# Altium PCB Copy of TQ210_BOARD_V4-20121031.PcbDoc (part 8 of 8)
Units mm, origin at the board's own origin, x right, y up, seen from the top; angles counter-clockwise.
Board outline 191.2 x 131.27 mm, 2 copper layers (TopLayer, BottomLayer); 362 components, 455 nets, 1594 pads, 630 vias.
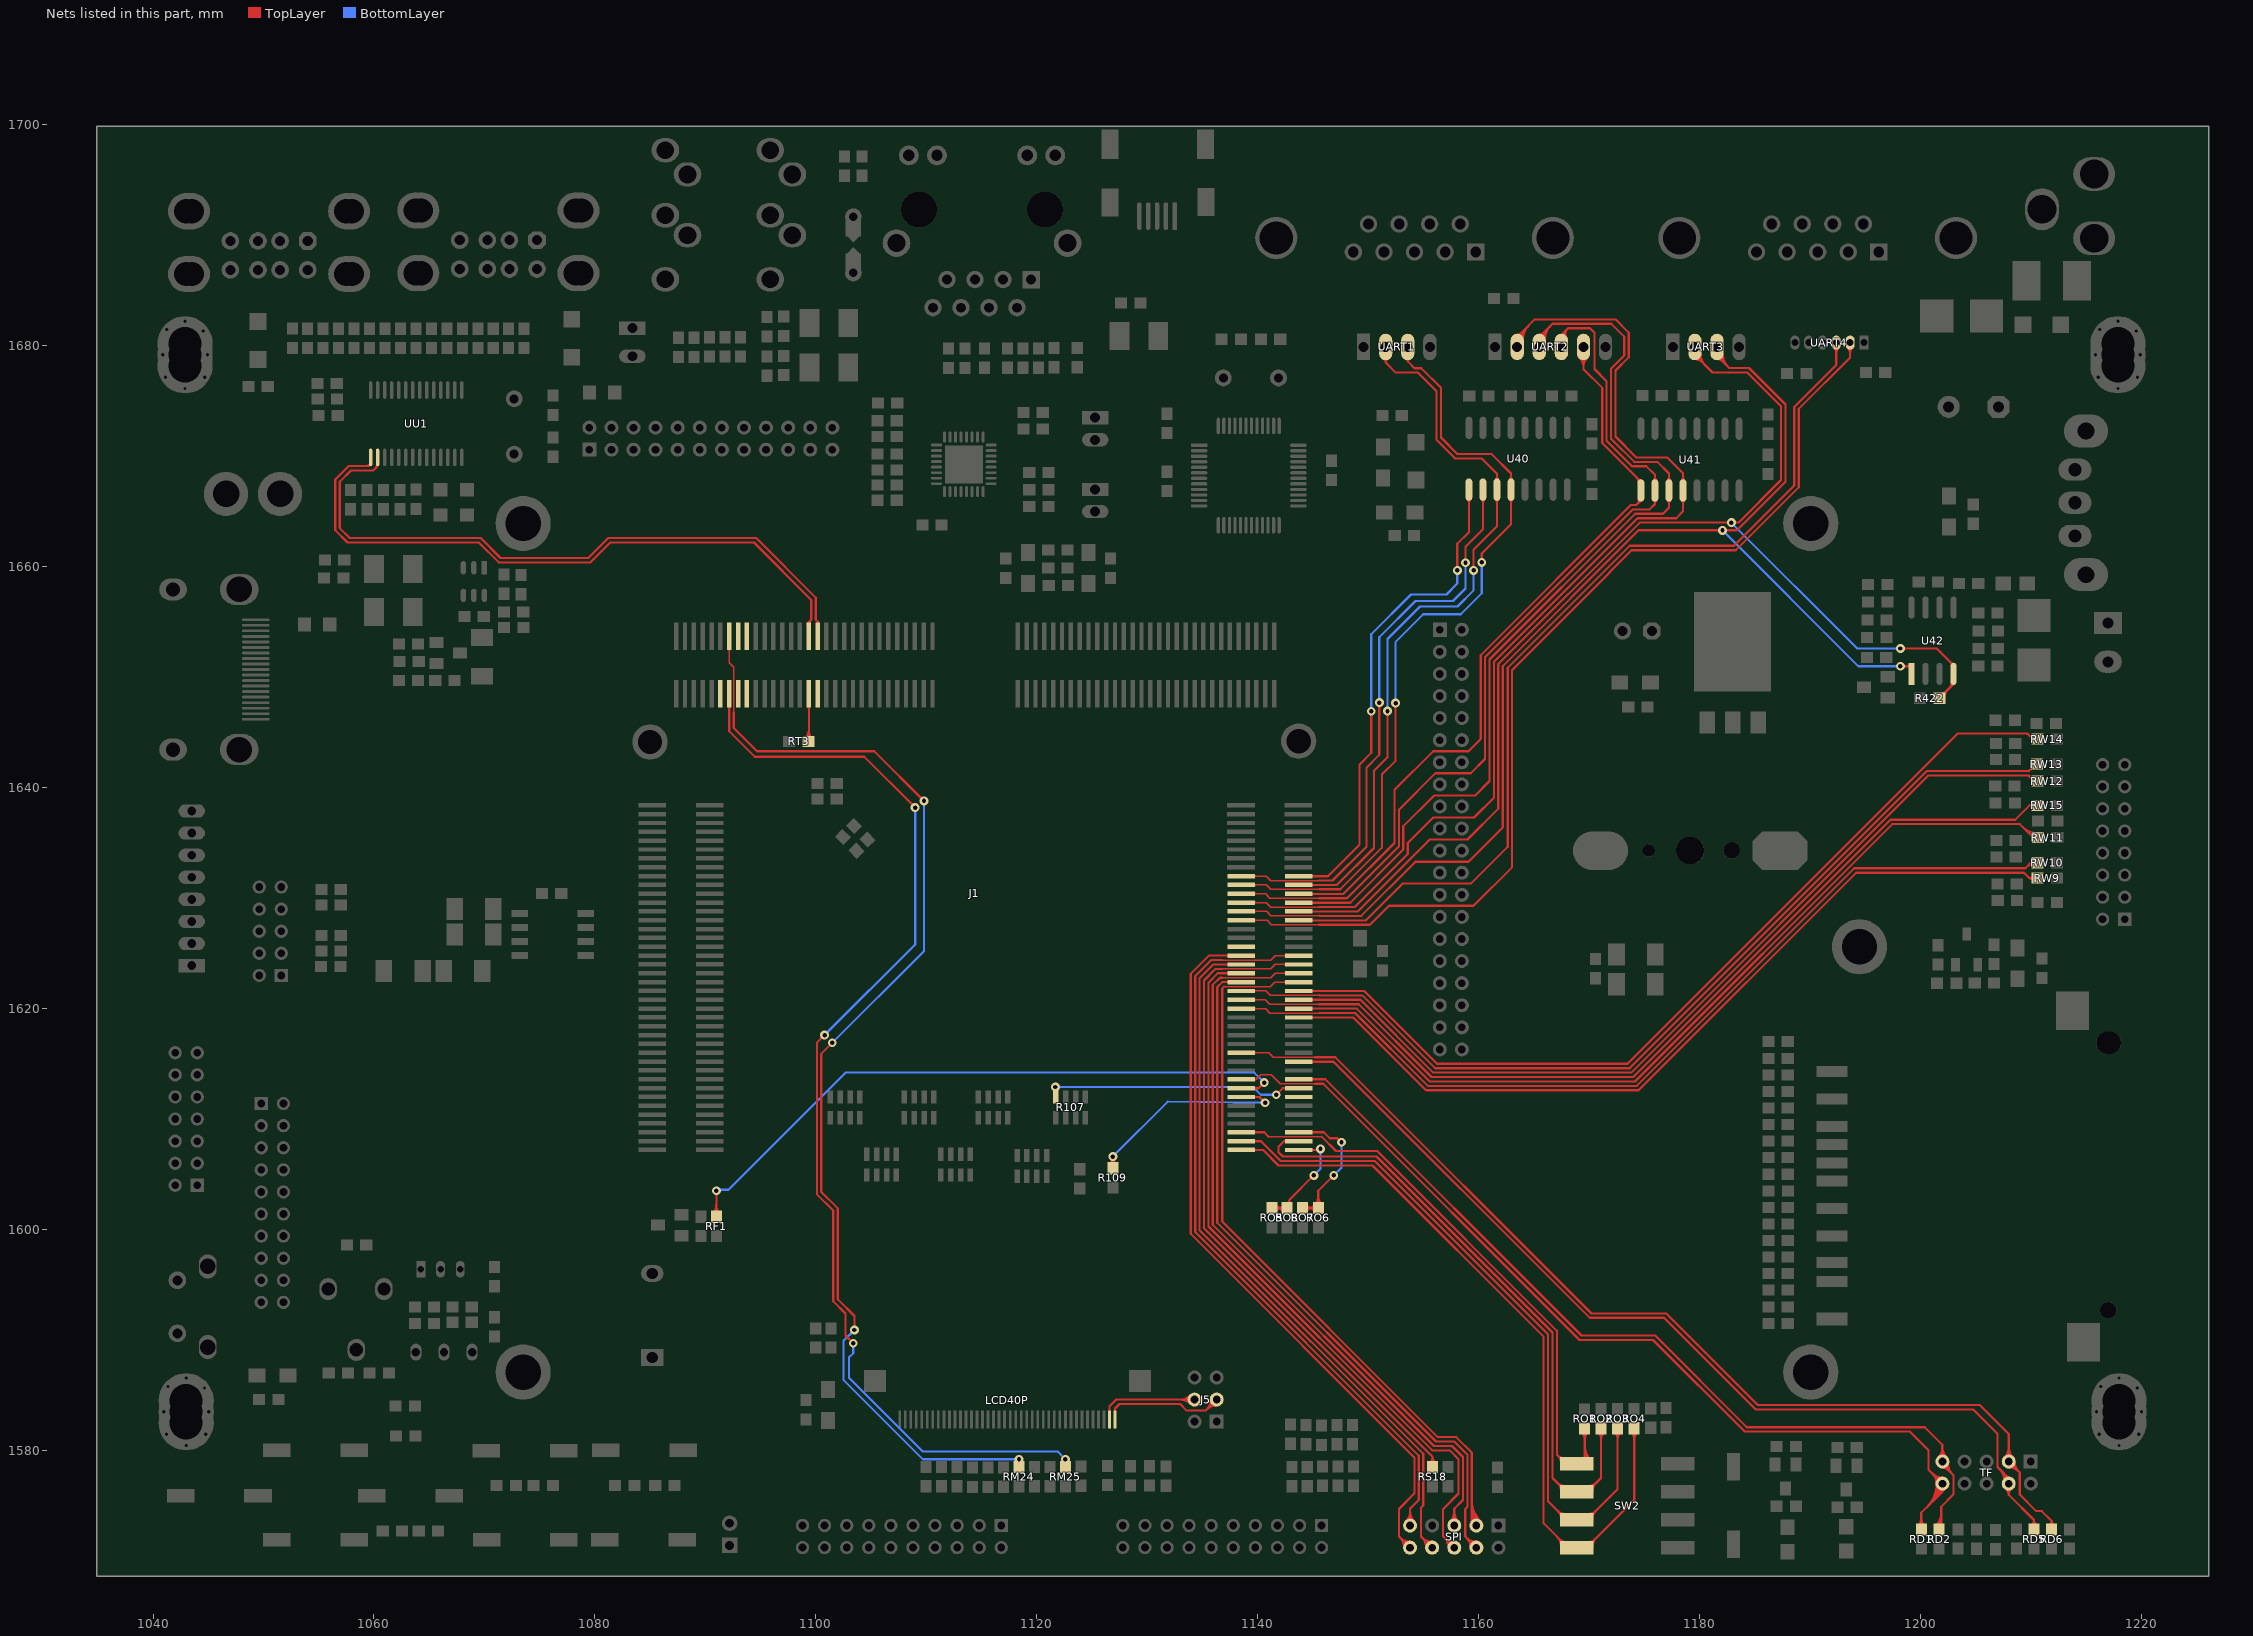
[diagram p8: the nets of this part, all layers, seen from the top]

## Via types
v1: diameter 1, hole 0.5, TopLayer to BottomLayer, 458 vias
v2: diameter 0.8, hole 0.4, TopLayer to BottomLayer, 172 vias

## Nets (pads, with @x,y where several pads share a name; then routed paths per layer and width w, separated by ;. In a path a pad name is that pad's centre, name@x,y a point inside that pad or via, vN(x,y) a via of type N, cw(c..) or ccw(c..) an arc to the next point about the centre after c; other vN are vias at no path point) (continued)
XMMC1DATA0: J1.263 RD2.2 TF.9 | length 89.9
  TopLayer w0.2: J1.263@1143.715,1613.595 1146.129,1613.595 1169.323,1590.4 1176,1590.4 1184.3,1582.1 1200.4,1582.1 1202,1580.5 TF.9@1202,1579 ; RD2.2@1201.417,1573.183 ccw(c1200.251,1574.349) 1201.9,1574.349 ; RD2.2@1201.559,1573.041 ccw(c1200.734,1573.866) 1201.9,1573.866 ; TF.9@1201.633,1579.367 ccw(c1200.746,1580.254) 1202,1580.254 ; RD2.2@1201.7,1572.9 ccw(c1201.217,1573.383) 1201.9,1573.383 ccw(c1202.183,1573.383) RD2.2@1201.983,1573.183 ; TF.9@1201.774,1579.226 ccw(c1201.229,1579.771) 1202,1579.771 ; RD2.2@1201.9,1572.85 1201.9,1574.9 1203,1576 1203,1577.75 1202.011,1578.739 TF.9@1202.011,1578.989 ; 1202,1579.824 ccw(c1202.846,1579.824) TF.9@1202.248,1579.226 ; 1202,1580.307 ccw(c1203.329,1580.307) TF.9@1202.389,1579.367 ; TF.9@1202.011,1578.454 cw(c1202.011,1577.765) 1202.498,1578.252 ; TF.9@1202.144,1578.968 ccw(c1202.759,1578.871) 1202.319,1578.431 ; TF.9@1202.342,1578.937 ccw(c1203.24,1578.796) 1202.597,1578.153 ; TF.9@1202.54,1578.906 ccw(c1203.72,1578.72) 1202.875,1577.875
XMMC1DATA1: J1.264 RD1.2 TF.10 | length 99
  TopLayer w0.135: J1.264@1138.515,1613.595 1139.9,1613.595 1140.305,1614 1141.234,1614 1142.039,1613.194 1145.194,1613.194 1145.2,1613.2 ; J1.264@1139.658,1613.501 cw(c1139.884,1613.275) 1139.884,1613.595 cw(c1139.884,1613.914) J1.264@1139.658,1613.688
  TopLayer w0.2: 1145.2,1613.2 1145.957,1613.2 1145.957,1613.195 1169.152,1590 1175.8,1590 1184.1,1581.7 1199.05,1581.7 1200.75,1580 1200.75,1578.25 TF.10@1202.011,1576.989 1202.011,1576.261 ; RD1.2@1199.817,1573.183 ccw(c1199.134,1573.866) 1200.1,1573.866 ccw(c1201.066,1573.866) RD1.2@1200.383,1573.183 ; RD1.2@1200.1,1572.85 1200.1,1574.35 1202.011,1576.261 ; 1200.583,1574.833 ccw(c1198.427,1576.989) 1201.476,1576.989 ccw(c1200.184,1576.989) 1201.098,1577.902 ccw(c1202.011,1578.815) TF.10@1202.011,1577.524 ; 1200.925,1575.175 ccw(c1199.11,1576.989) 1201.676,1576.989 ccw(c1200.867,1576.989) 1201.439,1577.561 ccw(c1202.011,1578.133) TF.10@1202.011,1577.324 ; 1201.266,1575.516 ccw(c1199.793,1576.989) TF.10@1201.876,1576.989 ; 1201.607,1575.857 ccw(c1200.476,1576.989) TF.10@1202.076,1576.989 ; TF.10@1201.851,1576.478 cw(c1201.784,1576.261) 1202.011,1576.261 ; 1201.949,1576.199 ccw(c1201.159,1576.989) TF.10@1202.276,1576.989 ; TF.10@1202.171,1576.478 ccw(c1202.239,1576.261) 1202.011,1576.261
XMMC1DATA2: J1.258 RD6.2 TF.3 | length 102.3
  TopLayer w0.135: J1.258@1138.515,1615.995 1141,1615.995 1141.401,1615.593 1145.193,1615.593 ; J1.258@1139.658,1615.901 cw(c1139.884,1615.675) 1139.884,1615.995 cw(c1139.884,1616.314) J1.258@1139.658,1616.088
  TopLayer w0.2: 1145.2,1615.6 1145.205,1615.595 1147.036,1615.595 1170.231,1592.4 1177,1592.4 1185.3,1584.1 1205.4,1584.1 1208.011,1581.489 TF.3@1208.011,1578.989 1209,1578 1209,1576 1210.5,1574.5 1211,1574.5 1211.9,1573.6 ; TF.3@1207.633,1579.367 ccw(c1206.719,1580.28) 1208.011,1580.28 ccw(c1209.303,1580.28) TF.3@1208.389,1579.367 ; TF.3@1207.774,1579.226 ccw(c1207.202,1579.798) 1208.011,1579.798 ccw(c1208.82,1579.798) TF.3@1208.248,1579.226 ; TF.3@1208.011,1578.454 cw(c1208.011,1577.162) 1208.924,1578.075 cw(c1209.838,1578.989) TF.3@1208.546,1578.989 ; TF.3@1208.011,1578.654 cw(c1208.011,1577.845) 1208.583,1578.417 cw(c1209.155,1578.989) TF.3@1208.346,1578.989 ; RD6.2@1211.697,1573.245 ccw(c1211.488,1573.6) 1211.9,1573.6 ; RD6.2@1211.9,1572.85 1211.9,1573.6 ; RD6.2@1212.103,1573.245 cw(c1212.312,1573.6) 1211.9,1573.6
XMMC1DATA3: J1.259 RD5.2 TF.4 | length 93.3
  TopLayer w0.2: J1.259@1143.715,1615.195 1146.871,1615.195 1170.065,1592 1176.8,1592 1178.162,1590.638 1185.1,1583.7 1204.8,1583.7 1207,1581.5 1207,1578.5 1208.011,1577.489 1208.011,1575.989 ; 1207.09,1578.41 cw(c1205.675,1576.995) TF.4@1207.676,1576.99 ; 1207.43,1578.07 cw(c1206.354,1576.993) TF.4@1207.876,1576.989 ; TF.4@1207.714,1576.544 cw(c1207.344,1575.989) 1208.011,1575.989 ; 1207.77,1577.73 cw(c1207.032,1576.992) TF.4@1208.076,1576.989 ; TF.4@1208.308,1576.544 ccw(c1208.678,1575.989) 1208.011,1575.989 ; RD5.2@1210.06,1573.22 ccw(c1209.7,1573.7) 1210.3,1573.7 ; RD5.2@1210.3,1572.85 1210.3,1573.7 ; RD5.2@1210.54,1573.22 cw(c1210.9,1573.7) 1210.3,1573.7 ; 1208.011,1575.989 1210.3,1573.7
XMMC2CDN: J1.92
XMMC2CLK: J1.96
XMMC2CMD: J1.95
XMMC2DATA0: J1.97 | length 0
  TopLayer w0.2: J1.97@1093.765,1653.697 J1.97@1093.775,1653.707
XMMC2DATA1: J1.98
XMMC2DATA2: J1.93 RM24.2 | length 105.7
  TopLayer w0.135: J1.93@1092.071,1652.553 cw(c1091.845,1652.327) 1092.165,1652.327 cw(c1092.484,1652.327) J1.93@1092.258,1652.553 ; J1.93@1092.165,1653.697 1092.165,1651.315 1092.564,1650.916 1092.564,1646.826
  TopLayer w0.2: 1092.581,1646.809 1092.581,1645.4 1094.681,1643.3 1105.3,1643.3 v2(1109.8,1638.8) ; v2(1101.5,1616.9) 1100.5,1615.9 1100.5,1603.4 1101.99,1601.91 1101.99,1593.676 1103.5,1592.166 v2(1103.5,1590.9)
  BottomLayer w0.2: v2(1101.5,1616.9) 1109.8,1625.2 v2(1109.8,1638.8) ; v2(1103.5,1590.9) 1102.5,1589.9 1102.5,1586.4 1109.7,1579.2 v2(1118.4,1579.2)
XMMC2DATA3: J1.94 RM25.2 | length 102.6
  TopLayer w0.2: J1.94@1092.175,1648.487 1092.175,1645.1 1094.475,1642.8 1104.4,1642.8 v2(1109,1638.2) ; v2(1100.8,1617.6) 1100.1,1616.9 1100.1,1603.2 1101.59,1601.71 1101.59,1593.51 1102.7,1592.4 1102.7,1590.4 v2(1103.4,1589.7)
  BottomLayer w0.2: v2(1100.8,1617.6) 1109,1625.8 v2(1109,1638.2) ; v2(1103.4,1589.7) 1103.4,1588.8 1103,1588.4 1103,1586.6 1109.7,1579.9 1121.9,1579.9 v2(1122.6,1579.2)
XMMC3CDN: J1.246 RW15.1 | length 86.5
  TopLayer w0.135: J1.246@1138.515,1620.795 1140.716,1620.795 1141.115,1620.395 1145.594,1620.395 ; J1.246@1139.658,1620.701 cw(c1139.884,1620.475) 1139.884,1620.795 cw(c1139.884,1621.114) J1.246@1139.658,1620.888
  TopLayer w0.2: 1145.595,1620.395 1145.6,1620.4 ; 1145.605,1620.395 1149.158,1620.395 1155.753,1613.8 1174.003,1613.8 1197.303,1637.1 1208.6,1637.1 1209.905,1638.405 ; RW15.1@1210.218,1638.217 ccw(c1209.905,1638.05) 1209.905,1638.405 ; RW15.1@1210.218,1638.593 cw(c1209.905,1638.76) 1209.905,1638.405 ; RW15.1@1210.621,1638.405 1209.905,1638.405
XMMC3CLK: J1.247 RW11.1 | length 82.7
  TopLayer w0.2: J1.247@1143.715,1619.995 1148.993,1619.995 1155.587,1613.4 1174.169,1613.4 1197.469,1636.7 1209,1636.7 RW11.1@1210.2,1635.5 ; 1209.268,1636.432 ccw(c1210.615,1637.778) RW11.1@1210.615,1635.874 ; 1209.61,1636.09 ccw(c1210.615,1637.095) RW11.1@1210.615,1635.674 ; 1209.951,1635.749 ccw(c1210.615,1636.412) RW11.1@1210.615,1635.474
XMMC3CMD: J1.245 RW12.1 | length 81.7
  TopLayer w0.2: J1.245@1143.715,1620.795 1149.324,1620.795 1155.919,1614.2 1173.837,1614.2 1200.737,1641.1 1209.8,1641.1 RW12.1@1210.3,1640.6 ; 1209.938,1640.962 ccw(c1210.157,1641.18) RW12.1@1210.338,1640.93 ; RW12.1@1210.084,1640.816 cw(c1209.873,1640.605) RW12.1@1210.171,1640.605 ; RW12.1@1210.104,1640.796 ccw(c1210.296,1640.987) RW12.1@1210.455,1640.767
XMMC3DATA0: J1.248 RW10.1 | length 86.1
  TopLayer w0.135: J1.248@1138.515,1619.995 1140.721,1619.995 1141.122,1619.593 1145.604,1619.593 ; J1.248@1139.658,1619.901 cw(c1139.884,1619.675) 1139.884,1619.995 cw(c1139.884,1620.314) J1.248@1139.658,1620.088
  TopLayer w0.2: 1145.605,1619.595 1148.827,1619.595 1155.422,1613 1174.334,1613 1194.034,1632.7 1209.5,1632.7 1210,1633.2 ; 1209.717,1632.917 cw(c1210.005,1632.628) RW10.1@1210.291,1632.919 ; 1209.86,1633.06 cw(c1210.147,1632.772) RW10.1@1210.431,1633.062 ; 1210.002,1633.202 cw(c1210.288,1632.916) RW10.1@1210.571,1633.205 ; RW10.1@1210.194,1633.338 cw(c1210,1633.406) 1210,1633.2 ; RW10.1@1210.197,1633.064 ccw(c1210,1632.989) 1210,1633.2 ; RW10.1@1210.4,1633.2 1210,1633.2
XMMC3DATA1: J1.249 RW9.1 | length 78.8
  TopLayer w0.2: J1.249@1143.715,1619.195 1148.661,1619.195 1155.256,1612.6 1174.5,1612.6 1194.2,1632.3 1209.4,1632.3 1209.895,1631.805 ; RW9.1@1210.221,1631.612 ccw(c1209.895,1631.433) 1209.895,1631.805 ; RW9.1@1210.221,1631.998 cw(c1209.895,1632.177) 1209.895,1631.805 ; RW9.1@1210.621,1631.805 1209.895,1631.805
XMMC3DATA2: J1.243 RW14.1 | length 83.1
  TopLayer w0.2: J1.243@1143.715,1621.595 1149.655,1621.595 1156.25,1615 1173.5,1615 ; 1173.503,1614.997 1203.406,1644.9 1209.7,1644.9 1210.195,1644.405 RW14.1@1210.621,1644.405 ; 1209.888,1644.712 ccw(c1210.101,1644.925) RW14.1@1210.303,1644.701 ; 1210.037,1644.563 ccw(c1210.242,1644.769) RW14.1@1210.437,1644.553
XMMC3DATA3: J1.244 RW13.1 | length 86.4
  TopLayer w0.135: J1.244@1138.515,1621.595 1140.753,1621.595 1141.154,1621.194 1145.594,1621.194
  TopLayer w0.2: 1145.6,1621.2 1145.605,1621.195 1149.49,1621.195 1156.084,1614.6 1173.7,1614.6 ; 1173.672,1614.6 1200.572,1641.5 1209.8,1641.5 1210.427,1642.127 RW13.1@1210.585,1642.127
XOM0: J1.275 RO6.2 RO7.1 | length 17.1
  TopLayer w0.2: J1.275@1143.715,1608.795 1146.005,1608.795 1146.532,1608.268 1147.232,1608.268 v2(1147.6,1607.9) ; RO7.1@1144.078,1601.944 1145.504,1601.944 1145.504,1603.504 v2(1146.9,1604.9) ; RO7.1@1144.361,1601.661 cw(c1145.044,1600.978) 1145.044,1601.944 cw(c1145.044,1602.91) RO7.1@1144.361,1602.227 ; RO7.1@1144.538,1601.944 cw(c1144.538,1600.976) RO6.2@1145.222,1601.661 ; RO7.1@1144.541,1601.944 ccw(c1144.541,1602.908) RO6.2@1145.222,1602.226 ; RO6.2@1145.222,1602.276 ccw(c1144.541,1602.958) 1145.504,1602.958 ; 1145.504,1602.96 ccw(c1146.472,1602.96) RO6.2@1145.788,1602.276
  BottomLayer w0.2: v2(1146.9,1604.9) 1147.6,1605.6 v2(1147.6,1607.9)
XOM1: J1.276 RO1.2 SW2.1 | length 61.1
  TopLayer w0.135: 1141,1608.4 1141.005,1608.395 1145.795,1608.395
  TopLayer w0.2: J1.276@1138.515,1608.795 1140.605,1608.795 1141,1608.4 ; J1.276@1139.635,1608.724 cw(c1139.806,1608.553) 1139.806,1608.795 cw(c1139.806,1609.036) J1.276@1139.635,1608.865 ; 1145.8,1608.4 1147.1,1607.1 1150.834,1607.1 1167.1,1590.834 1167.1,1579.6 1167.9,1578.8 SW2.1@1169.9,1578.8 ; 1167.15,1579.55 ccw(c1167.791,1580.191) SW2.1@1167.926,1579.294 ; 1167.217,1579.483 cw(c1166.534,1578.8) SW2.1@1167.5,1578.8 ; SW2.1@1167.43,1579.27 ccw(c1167.864,1579.704) SW2.1@1167.955,1579.097 ; RO1.2@1169.339,1581.633 cw(c1168.656,1580.95) 1169.622,1580.95 cw(c1170.588,1580.95) RO1.2@1169.905,1581.633 ; SW2.1@1169.446,1579.154 ccw(c1169.023,1579.577) 1169.622,1579.577 ; SW2.1@1169.622,1578.922 RO1.2@1169.622,1581.966 ; 1169.622,1579.471 ccw(c1170.471,1579.471) SW2.1@1169.871,1578.871 ; 1169.622,1579.954 ccw(c1170.954,1579.954) SW2.1@1170.012,1579.012 ; 1169.622,1580.437 ccw(c1171.437,1580.437) SW2.1@1170.154,1579.154
XOM2: J1.277 RO2.1 SW2.2 | length 63.2
  TopLayer w0.2: J1.277@1143.715,1607.995 1142.395,1607.995 1141.9,1607.5 1141.9,1607 1142.3,1606.6 1150.769,1606.6 1166.7,1590.669 1166.7,1577.5 SW2.2@1168.2,1576 ; 1167.044,1577.156 ccw(c1168,1578.112) SW2.2@1168,1576.76 ; 1167.189,1577.011 cw(c1166.438,1576.26) SW2.2@1167.5,1576.26 ; 1167.385,1576.815 ccw(c1168,1577.429) SW2.2@1168,1576.56 ; SW2.2@1167.53,1576.67 cw(c1167.121,1576.26) SW2.2@1167.7,1576.26 ; SW2.2@1169.8,1576.56 ccw(c1169.8,1577.429) 1170.415,1576.815 ; SW2.2@1169.8,1576.76 ccw(c1169.8,1578.112) 1170.756,1577.156 ; SW2.2@1169.86,1576.26 1171.1,1577.5 RO2.1@1171.1,1582 ; SW2.2@1170.1,1576.26 cw(c1170.679,1576.26) SW2.2@1170.27,1576.67 ; SW2.2@1170.3,1576.26 cw(c1171.362,1576.26) 1170.611,1577.011 ; RO2.1@1170.817,1581.667 cw(c1170.134,1580.984) 1171.1,1580.984 cw(c1172.066,1580.984) RO2.1@1171.383,1581.667
XOM3: J1.278 RO3.1 SW2.3 | length 70.2
  TopLayer w0.2: J1.278@1138.515,1607.995 1140.305,1607.995 1142.1,1606.2 1150.603,1606.2 1166.3,1590.503 1166.3,1575.4 SW2.3@1168.2,1573.5 ; J1.278@1139.635,1607.924 cw(c1139.806,1607.753) 1139.806,1607.995 cw(c1139.806,1608.236) J1.278@1139.635,1608.065 ; 1167.112,1574.588 ccw(c1168,1575.475) SW2.3@1168,1574.22 ; 1167.161,1574.539 cw(c1166.341,1573.72) SW2.3@1167.5,1573.72 ; SW2.3@1167.454,1574.246 ccw(c1168,1574.793) SW2.3@1168,1574.02 ; SW2.3@1167.502,1574.198 cw(c1167.024,1573.72) SW2.3@1167.7,1573.72 ; SW2.3@1169.8,1574.02 ccw(c1169.8,1574.793) SW2.3@1170.346,1574.246 ; SW2.3@1169.8,1574.22 ccw(c1169.8,1575.475) 1170.688,1574.588 ; SW2.3@1169.82,1573.72 1172.6,1576.5 RO3.1@1172.6,1582 ; SW2.3@1170.1,1573.72 cw(c1170.776,1573.72) SW2.3@1170.298,1574.198 ; SW2.3@1170.3,1573.72 cw(c1171.459,1573.72) 1170.639,1574.539 ; RO3.1@1172.317,1581.667 cw(c1171.634,1580.984) 1172.6,1580.984 cw(c1173.566,1580.984) RO3.1@1172.883,1581.667
XOM4: J1.279 RO5.2 RO8.1 | length 14.7
  TopLayer w0.2: RO5.2@1141.305,1601.943 RO8.1@1142.657,1601.943 ; RO5.2@1141.588,1601.661 cw(c1142.271,1600.978) 1142.271,1601.943 cw(c1142.271,1602.909) RO5.2@1141.588,1602.226 ; RO5.2@1141.661,1601.943 cw(c1141.661,1600.905) RO8.1@1142.395,1601.639 ; RO5.2@1141.764,1601.943 ccw(c1141.764,1602.836) RO8.1@1142.395,1602.205 ; 1142.144,1601.943 cw(c1142.144,1601.387) RO8.1@1142.537,1601.781 ; RO8.1@1142.616,1602.367 ccw(c1142.563,1602.7) 1142.9,1602.7 ; RO8.1@1142.647,1602.17 ccw(c1142.6,1602.466) RO8.1@1142.9,1602.466 ; RO8.1@1142.9,1601.8 1142.9,1602.7 v2(1145.1,1604.9) ; J1.279@1143.715,1607.195 1145.595,1607.195 v2(1145.7,1607.3) ; J1.279@1144.835,1607.124 cw(c1145.006,1606.953) 1145.006,1607.195 cw(c1145.006,1607.436) J1.279@1144.835,1607.265
  BottomLayer w0.2: v2(1145.1,1604.9) 1145.7,1605.5 v2@1145.7,1607.2
XOM5: J1.280 RO4.1 SW2.4 | length 74.9
  TopLayer w0.2: J1.280@1138.515,1607.206 1140.494,1607.206 1141.9,1605.8 1150.4,1605.8 1165.9,1590.3 1165.9,1573.4 SW2.4@1168.3,1571 ; J1.280@1139.635,1607.135 cw(c1139.806,1606.965) 1139.806,1607.206 cw(c1139.806,1607.447) J1.280@1139.635,1607.277 ; 1167.062,1572.238 cw(c1166.003,1571.18) SW2.4@1167.5,1571.18 ; 1167.351,1571.949 ccw(c1168,1572.597) SW2.4@1168,1571.68 ; 1167.403,1571.897 cw(c1166.686,1571.18) SW2.4@1167.7,1571.18 ; SW2.4@1169.78,1571.18 1174.1,1575.5 RO4.1@1174.1,1582 ; SW2.4@1169.8,1571.48 ccw(c1169.8,1572.156) SW2.4@1170.278,1571.678 ; SW2.4@1169.8,1571.68 ccw(c1169.8,1572.839) 1170.619,1572.019 ; SW2.4@1170.1,1571.18 cw(c1170.873,1571.18) SW2.4@1170.326,1571.726 ; SW2.4@1170.3,1571.18 cw(c1171.555,1571.18) 1170.668,1572.068 ; RO4.1@1173.817,1581.667 cw(c1173.134,1580.984) 1174.1,1580.984 cw(c1175.066,1580.984) RO4.1@1174.383,1581.667
XPWMTOUT0: J1.265 R107.4 | length 22.6
  TopLayer w0.2: v2(1141.7,1612.2) 1142.284,1612.784 J1.265@1143.725,1612.784
  BottomLayer w0.2: v2(1121.7,1612.9) 1139.6,1612.9 1140.3,1612.2 v2(1141.7,1612.2)
XPWMTOUT1: J1.266 RF1.2 | length 61
  TopLayer w0.2: RF1.2@1090.712,1601.482 ccw(c1090.03,1602.167) 1090.997,1602.165 ; RF1.2@1090.995,1601.048 v2(1091,1603.5) ; 1090.997,1602.163 ccw(c1091.962,1602.161) RF1.2@1091.278,1601.48 ; J1.266@1138.525,1612.784 1140.084,1612.784 v2(1140.6,1613.3) ; J1.266@1139.635,1612.724 cw(c1139.781,1612.578) 1139.781,1612.784 ; J1.266@1139.635,1612.865 ccw(c1139.831,1613.061) 1139.831,1612.784
  BottomLayer w0.2: v2(1091,1603.5) v2@1091,1603.603 ; v2@1091.057,1603.604 1092.092,1603.604 1102.688,1614.2 1139.7,1614.2 v2(1140.6,1613.3)
XPWMTOUT2: J1.267
XPWMTOUT3: J1.268 R109.2 | length 21.2
  TopLayer w0.2: R109.2@1126.617,1605.883 ccw(c1125.934,1606.566) 1126.9,1606.566 ccw(c1127.866,1606.566) R109.2@1127.183,1605.883 ; R109.2@1126.9,1605.55 v2(1126.9,1606.6) ; J1.268@1138.515,1611.995 1140.172,1611.995 v2(1140.689,1611.478) ; J1.268@1139.635,1611.924 cw(c1139.806,1611.753) 1139.806,1611.995 cw(c1139.806,1612.236) J1.268@1139.635,1612.065
  BottomLayer w0.2: v2(1126.9,1606.6) 1131.879,1611.578 v2(1140.689,1611.478)
XPWRRGTON: J1.234
XSPICLK0: J1.236 SPI.10 | length 69.9
  TopLayer w0.2: J1.236@1138.515,1624.795 1135.595,1624.795 1133.95,1623.15 1133.95,1599.604 1154.2,1579.354 1154.2,1576.1 1152.8,1574.7 1152.8,1572.2 SPI.10@1153.811,1571.189 ; SPI.10@1153.276,1571.189 ccw(c1151.984,1571.189) 1152.898,1572.102 ccw(c1153.811,1573.015) SPI.10@1153.811,1571.724 ; SPI.10@1153.476,1571.189 ccw(c1152.667,1571.189) 1153.239,1571.761 ccw(c1153.811,1572.333) SPI.10@1153.811,1571.524
XSPICLK1: J1.239 SPI.5 | length 71.6
  TopLayer w0.135: 1136.795,1622.795 1141.185,1622.795 1141.585,1623.195 J1.239@1143.715,1623.195 ; J1.239@1142.571,1623.101 ccw(c1142.345,1622.875) 1142.345,1623.195 ccw(c1142.345,1623.514) J1.239@1142.571,1623.288
  TopLayer w0.2: 1136.795,1622.795 1136.595,1622.795 1135.95,1622.15 1135.95,1600.432 1155.982,1580.4 1157.6,1580.4 1158.6,1579.4 1158.6,1575.5 1157.811,1574.711 SPI.5@1157.811,1573.189 ; SPI.5@1157.433,1573.567 ccw(c1156.519,1574.48) 1157.811,1574.48 ccw(c1159.103,1574.48) SPI.5@1158.189,1573.567 ; SPI.5@1157.574,1573.426 ccw(c1157.002,1573.998) 1157.811,1573.998 ccw(c1158.62,1573.998) SPI.5@1158.048,1573.426
XSPICSN0: J1.237 RS18.1 | length 63.5
  TopLayer w0.135: 1136.796,1623.593 1141.194,1623.593 1141.595,1623.995 J1.237@1143.715,1623.995 ; J1.237@1142.571,1623.901 ccw(c1142.345,1623.675) 1142.345,1623.995 ccw(c1142.345,1624.314) J1.237@1142.571,1624.088
  TopLayer w0.2: 1136.795,1623.595 1136.195,1623.595 1135.15,1622.55 1135.15,1600.101 1155.85,1579.401 ; RS18.1@1155.595,1578.858 ccw(c1155.145,1579.401) 1155.85,1579.401 ; RS18.1@1155.85,1578.5 1155.85,1579.401 ; RS18.1@1156.105,1578.858 cw(c1156.555,1579.401) 1155.85,1579.401
XSPICSN1: J1.241 SPI.3 | length 73
  TopLayer w0.135: 1136.995,1621.995 1141.152,1621.995 1141.552,1622.395 J1.241@1143.715,1622.395 ; J1.241@1142.571,1622.301 ccw(c1142.345,1622.075) 1142.345,1622.395 ccw(c1142.345,1622.714) J1.241@1142.571,1622.488
  TopLayer w0.2: 1136.995,1621.995 1136.795,1621.795 1136.795,1600.719 1156.314,1581.2 1158,1581.2 1159.4,1579.8 1159.4,1573.6 SPI.3@1159.811,1573.189 ; 1159.4,1574.024 ccw(c1160.646,1574.024) SPI.3@1159.765,1573.143 ; 1159.4,1574.507 ccw(c1161.129,1574.507) SPI.3@1159.906,1573.284 ; 1159.4,1574.99 ccw(c1161.612,1574.99) SPI.3@1160.048,1573.426 ; 1159.4,1575.473 ccw(c1162.095,1575.473) SPI.3@1160.189,1573.567
XSPIMISO0: J1.235 SPI.9 | length 72.4
  TopLayer w0.135: 1136.796,1624.396 1141.196,1624.396 1141.595,1624.795 J1.235@1143.715,1624.795 ; J1.235@1142.571,1624.701 ccw(c1142.345,1624.475) 1142.345,1624.795 ccw(c1142.345,1625.114) J1.235@1142.571,1624.888
  TopLayer w0.2: 1136.795,1624.395 1135.795,1624.395 1134.35,1622.95 1134.35,1599.77 1154.6,1579.52 1154.6,1575.5 1153.811,1574.711 SPI.9@1153.811,1573.189 ; SPI.9@1153.433,1573.567 ccw(c1152.519,1574.48) 1153.811,1574.48 ccw(c1155.103,1574.48) SPI.9@1154.189,1573.567 ; SPI.9@1153.574,1573.426 ccw(c1153.002,1573.998) 1153.811,1573.998 ccw(c1154.62,1573.998) SPI.9@1154.048,1573.426
XSPIMISO1: J1.240 SPI.6 | length 69.1
  TopLayer w0.2: J1.240@1138.515,1623.195 1136.4,1623.195 1135.55,1622.345 1135.55,1600.267 1155.817,1580 1157.4,1580 1158.2,1579.2 1158.2,1576.1 1156.8,1574.7 1156.8,1572.2 SPI.6@1157.811,1571.189 ; SPI.6@1157.276,1571.189 ccw(c1155.984,1571.189) 1156.898,1572.102 ccw(c1157.811,1573.015) SPI.6@1157.811,1571.724 ; SPI.6@1157.476,1571.189 ccw(c1156.667,1571.189) 1157.239,1571.761 ccw(c1157.811,1572.333) SPI.6@1157.811,1571.524
XSPIMOSI0: J1.238 SPI.8 | length 68
  TopLayer w0.2: J1.238@1138.515,1623.995 1135.995,1623.995 1134.75,1622.75 1134.75,1599.935 1155,1579.685 1155,1575 1154.8,1574.8 1154.8,1572.2 SPI.8@1155.811,1571.189 ; SPI.8@1155.276,1571.189 ccw(c1153.984,1571.189) 1154.898,1572.102 ccw(c1155.811,1573.015) SPI.8@1155.811,1571.724 ; SPI.8@1155.476,1571.189 ccw(c1154.667,1571.189) 1155.239,1571.761 ccw(c1155.811,1572.333) SPI.8@1155.811,1571.524
XSPIMOSI1: J1.242 SPI.4 | length 67.3
  TopLayer w0.2: J1.242@1138.515,1622.395 1136.795,1622.395 1136.35,1621.95 1136.35,1600.598 1156.148,1580.8 1157.8,1580.8 1159,1579.6 1159,1574.9 1158.8,1574.7 1158.8,1572.2 SPI.4@1159.811,1571.189 ; SPI.4@1159.276,1571.189 ccw(c1157.984,1571.189) 1158.898,1572.102 ccw(c1159.811,1573.015) SPI.4@1159.811,1571.724 ; SPI.4@1159.476,1571.189 ccw(c1158.667,1571.189) 1159.239,1571.761 ccw(c1159.811,1572.333) SPI.4@1159.811,1571.524
XUCTSN0: J1.217 U40.9 | length 45.6
  TopLayer w0.2: J1.217@1143.725,1631.984 1146.384,1631.984 ; 1146.395,1631.995 1149.223,1634.823 1149.223,1642.085 1150.29,1643.151 v2(1150.29,1646.917) ; v2(1158.09,1659.674) 1158.09,1662.09 1159.138,1663.138 U40.9@1159.138,1666.989 ; U40.9@1158.994,1666.133 cw(c1158.644,1665.784) 1159.138,1665.784 cw(c1159.633,1665.784) U40.9@1159.283,1666.133
  BottomLayer w0.2: v2(1150.29,1646.917) 1150.29,1653.89 1153.9,1657.5 1157.1,1657.5 1158.09,1658.49 v2(1158.09,1659.674)
XUCTSN1: J1.221 U41.9 UART2.5 | length 73.4
  TopLayer w0.2: J1.221@1143.725,1630.384 1147.784,1630.384 1152.4,1635 1152.4,1639.8 1155.9,1643.3 1159.1,1643.3 1160.2,1644.4 1160.2,1652 1173.8,1665.6 1174.3,1665.6 1174.71,1666.01 1174.71,1667.69 1171.2,1671.2 1171.2,1676.2 1169.508,1677.892 UART2.5@1169.508,1679.902 ; UART2.5@1169.154,1678.948 cw(c1168.301,1678.095) 1169.508,1678.095 cw(c1170.715,1678.095) UART2.5@1169.861,1678.948 ; UART2.5@1169.296,1679.09 cw(c1168.784,1678.578) 1169.508,1678.578 cw(c1170.232,1678.578) UART2.5@1169.72,1679.09 ; 1174.313,1668.087 cw(c1173.849,1667.623) U41.9@1174.505,1667.623 ; 1174.395,1665.695 ccw(c1174.07,1666.021) U41.9@1174.513,1666.145 ; 1174.474,1667.926 ccw(c1174.71,1668.161) U41.9@1174.71,1667.828
XUHDN: J1.111 UU1.15 | length 61.3
  TopLayer w0.2: 1059.258,1669.123 ccw(c1059.258,1669.691) UU1.15@1059.66,1669.289 ; 1059.54,1669.14 cw(c1059.695,1668.984) UU1.15@1059.695,1669.204 ; UU1.15@1059.695,1669.904 1059.695,1669.295 1059.523,1669.123 1057.723,1669.123 1056.5,1667.9 1056.5,1663.3 1057.6,1662.2 1069.5,1662.2 1071.3,1660.4 1079.6,1660.4 1081.4,1662.2 1094.4,1662.2 1099.6,1657 1099.6,1655.225 ; J1.111@1099.267,1654.727 cw(c1099.521,1654.779) 1099.337,1654.962 ; J1.111@1099.297,1654.82 ccw(c1099.13,1655) 1099.375,1655 ; J1.111@1099.375,1653.687 1099.375,1655 ; 1099.375,1654.963 ccw(c1099.581,1654.963) J1.111@1099.435,1654.818 ; J1.111@1099.463,1654.767 cw(c1099.957,1654.868) 1099.6,1655.225 ; 1099.375,1655 1099.6,1655.225
XUHDP: J1.113 UU1.16 | length 60.8
  TopLayer w0.2: 1060.157,1668.957 ccw(c1059.86,1669.254) UU1.16@1060.28,1669.254 ; UU1.16@1060.33,1669.904 1060.33,1669.13 1059.923,1668.723 1057.923,1668.723 1056.9,1667.7 1056.9,1663.5 1057.8,1662.6 1069.666,1662.6 1071.466,1660.8 1079.4,1660.8 1081.2,1662.6 1094.6,1662.6 1100,1657.2 1100,1655.2 1100.175,1655.025 J1.113@1100.175,1653.687 ; J1.113@1100.094,1654.818 ccw(c1099.898,1655.013) 1100.175,1655.013 ; 1100.154,1655.046 cw(c1099.883,1654.775) J1.113@1100.264,1654.737 ; 1100.175,1654.963 ccw(c1100.381,1654.963) J1.113@1100.235,1654.818
XUHOVERCUR: J1.112 RT3.2 | length 6.7
  TopLayer w0.2: RT3.2@1099.067,1644.483 ccw(c1098.324,1645.226) 1099.375,1645.226 ; RT3.2@1099.209,1644.341 ccw(c1098.807,1644.743) 1099.375,1644.743 ; J1.112@1099.294,1647.376 cw(c1099.098,1647.181) 1099.375,1647.181 ; RT3.2@1099.375,1644.125 J1.112@1099.375,1648.487 ; 1099.375,1645.105 ccw(c1100.255,1645.105) RT3.2@1099.633,1644.483 ; 1099.375,1647.231 cw(c1099.581,1647.231) J1.112@1099.435,1647.376
XUHPWREN: J1.114
XURTSN0: J1.218 U40.10 | length 52.7
  TopLayer w0.135: J1.218@1138.515,1631.995 1140.805,1631.995 1141.207,1631.594 1145.594,1631.594 ; J1.218@1139.658,1631.901 cw(c1139.884,1631.675) 1139.884,1631.995 cw(c1139.884,1632.314) J1.218@1139.658,1632.088
  TopLayer w0.2: 1145.595,1631.595 1146.795,1631.595 1149.858,1634.658 1149.858,1641.805 1151.026,1642.974 v2(1151.026,1647.698) ; v2(1158.825,1660.367) 1158.825,1661.825 1160.408,1663.408 U40.10@1160.408,1666.989 ; U40.10@1160.264,1666.133 cw(c1159.914,1665.784) 1160.408,1665.784 cw(c1160.903,1665.784) U40.10@1160.553,1666.133
  BottomLayer w0.2: v2(1151.026,1647.698) 1151.025,1653.625 1154.3,1656.9 1157.7,1656.9 1158.825,1658.025 v2(1158.825,1660.367)
XURTSN1: J1.222 U41.10 UART2.4 | length 87.4
  TopLayer w0.135: J1.222@1138.515,1630.395 1140.72,1630.395 1141.12,1629.995 1145.595,1629.995 ; J1.222@1139.658,1630.301 cw(c1139.884,1630.075) 1139.884,1630.395 cw(c1139.884,1630.714) J1.222@1139.658,1630.488
  TopLayer w0.2: 1145.6,1630 1145.595,1629.995 1148.095,1629.995 1152.8,1634.7 1152.8,1638 1156.1,1641.3 1159.3,1641.3 1160.6,1642.6 1160.6,1651.8 1174,1665.2 1175.5,1665.2 1175.98,1665.68 1175.98,1668.32 1175.2,1669.1 1173.9,1669.1 1171.6,1671.4 1171.6,1676.8 1170.5,1677.9 1170.5,1681.2 1170.1,1681.6 1168.1,1681.6 ; UART2.4@1167.508,1679.902 1167.508,1681.008 1168.1,1681.6 ; UART2.4@1167.597,1680.546 cw(c1168.111,1680.801) 1167.706,1681.206 ; UART2.4@1167.777,1680.635 cw(c1168.375,1680.931) 1167.903,1681.403 ; UART2.4@1167.956,1680.724 cw(c1168.638,1681.061) 1168.1,1681.6 ; U41.10@1175.835,1666.056 cw(c1175.486,1665.706) 1175.98,1665.706 cw(c1176.474,1665.706) U41.10@1176.125,1666.056 ; U41.10@1175.835,1667.768 ccw(c1175.486,1668.118) 1175.98,1668.118 ccw(c1176.474,1668.118) U41.10@1176.125,1667.768
XURXD0: J1.220 U40.12 UART1.3 | length 75.3
  TopLayer w0.135: J1.220@1138.515,1631.195 1140.805,1631.195 1141.205,1630.795 1145.595,1630.795 ; J1.220@1139.658,1631.101 cw(c1139.884,1630.875) 1139.884,1631.195 cw(c1139.884,1631.514) J1.220@1139.658,1631.288
  TopLayer w0.2: 1145.6,1630.8 1147.5,1630.8 1151.255,1634.555 1151.255,1641.196 1152.5,1642.44 v2(1152.498,1647.658) ; UART1.3@1153.438,1678.827 cw(c1153.36,1678.6) 1153.6,1678.6 ; UART1.3@1153.6,1679.9 1153.6,1678.6 ; UART1.3@1153.762,1678.827 ccw(c1153.84,1678.6) 1153.6,1678.6 ; v2(1160.3,1660.4) 1160.3,1661.2 1162.948,1663.848 1162.948,1668.452 1161.2,1670.2 1158.1,1670.2 1156.6,1671.7 1156.6,1676.2 1154.819,1677.981 1154.219,1677.981 1153.6,1678.6 ; U40.12@1162.804,1666.133 cw(c1162.454,1665.784) 1162.948,1665.784 cw(c1163.443,1665.784) U40.12@1163.093,1666.133 ; U40.12@1162.804,1667.845 ccw(c1162.454,1668.195) 1162.948,1668.195 ccw(c1163.443,1668.195) U40.12@1163.093,1667.845
  BottomLayer w0.2: v2(1152.498,1647.658) v2@1152.498,1647.8 ; v2@1152.5,1647.8 1152.5,1653.2 1155,1655.7 1158.4,1655.7 1160.3,1657.6 v2(1160.3,1660.4)
XURXD1: J1.224 U41.12 UART2.2 | length 101.7
  TopLayer w0.135: J1.224@1138.515,1629.595 1140.781,1629.595 1141.182,1629.194 1145.594,1629.194 ; J1.224@1139.658,1629.501 cw(c1139.884,1629.275) 1139.884,1629.595 cw(c1139.884,1629.914) J1.224@1139.658,1629.688
  TopLayer w0.2: 1145.595,1629.195 1145.6,1629.2 1148.8,1629.2 1153.6,1634 1153.6,1635 1155.9,1637.3 1159.6,1637.3 1161.4,1639.1 1161.4,1651.4 1174.4,1664.4 1177.9,1664.4 1178.52,1665.02 1178.52,1668.48 1177.1,1669.9 1174.3,1669.9 1172.4,1671.8 1172.4,1677.766 1173.6,1678.966 1173.6,1681.2 1172.4,1682.4 1165.1,1682.4 1163.508,1680.808 UART2.2@1163.508,1679.902 ; UART2.2@1163.508,1681.002 ccw(c1163.508,1681.471) 1163.839,1681.139 ; UART2.2@1163.608,1680.502 cw(c1164.587,1680.502) 1163.895,1681.195 ; UART2.2@1163.808,1680.502 cw(c1165.27,1680.502) 1164.236,1681.536 ; UART2.2@1164.008,1680.502 cw(c1165.953,1680.502) 1164.578,1681.878 ; U41.12@1178.375,1666.056 cw(c1178.026,1665.706) 1178.52,1665.706 cw(c1179.014,1665.706) U41.12@1178.665,1666.056 ; U41.12@1178.375,1667.768 ccw(c1178.026,1668.118) 1178.52,1668.118 ccw(c1179.014,1668.118) U41.12@1178.665,1667.768
XURXD2: J1.226 U42.1 UART3.3 | length 117.1
  TopLayer w0.135: J1.226@1138.515,1628.795 1140.814,1628.795 1141.213,1628.396 1145.596,1628.396 ; J1.226@1139.658,1628.701 cw(c1139.884,1628.475) 1139.884,1628.795 cw(c1139.884,1629.114) J1.226@1139.658,1628.888
  TopLayer w0.2: 1145.6,1628.4 1145.605,1628.395 1149.395,1628.395 1154.3,1633.3 1159.1,1633.3 1162.2,1636.4 1162.2,1651 1174.5,1663.3 1183.403,1663.3 1187.8,1667.697 1187.8,1674.7 1184.5,1678 1182.7,1678 1181.6,1679.1 UART3.3@1181.6,1680 ; UART3.3@1181.6,1678.8 cw(c1181.6,1678.076) 1182.112,1678.588 ; UART3.3@1181.9,1679.3 ccw(c1183.107,1679.3) 1182.254,1678.446 ; UART3.3@1182.1,1679.3 ccw(c1183.79,1679.3) 1182.595,1678.105 ; v2(1198.2,1651) 1199.2,1651 1199.209,1650.991 U42.1@1199.209,1650.311 ; 1198.7,1651 ccw(c1198.7,1651.545) U42.1@1199.085,1651.16 ; 1198.872,1651 cw(c1198.872,1650.7) U42.1@1199.085,1650.912
  BottomLayer w0.2: v2(1182.1,1663.3) 1194.4,1651 v2(1198.2,1651)
XURXD3: J1.228 UART4.2 | length 94.2
  TopLayer w0.135: J1.228@1138.515,1627.995 1140.861,1627.995 1141.262,1627.594 1145.582,1627.594 ; J1.228@1139.658,1627.901 cw(c1139.884,1627.675) 1139.884,1627.995 cw(c1139.884,1628.314) J1.228@1139.658,1628.088
  TopLayer w0.2: 1145.588,1627.588 1150.188,1627.588 1151.908,1629.308 1159.558,1629.308 1163.05,1632.8 1163.05,1650.65 1171.883,1659.483 ; 1171.866,1659.5 1173.866,1661.5 1183.3,1661.5 1189,1667.2 1189,1674.3 1193.65,1678.95 UART4.2@1193.65,1680.3 ; UART4.2@1193.433,1679.855 cw(c1192.91,1679.332) 1193.65,1679.332 cw(c1194.39,1679.332) UART4.2@1193.867,1679.855
XUTXD0: J1.219 U40.11 UART1.2 | length 69.3
  TopLayer w0.2: J1.219@1143.725,1631.184 1147.184,1631.184 ; 1147.2,1631.2 1150.544,1634.544 1150.544,1641.526 1151.763,1642.745 v2(1151.763,1646.936) ; UART1.2@1151.381,1678.851 cw(c1151.21,1678.5) 1151.6,1678.5 ; UART1.2@1151.6,1679.9 1151.6,1678.5 ; UART1.2@1151.819,1678.851 ccw(c1151.99,1678.5) 1151.6,1678.5 ; v2(1159.563,1659.674) 1159.563,1661.563 1161.678,1663.678 1161.678,1668.422 1160.3,1669.8 1157.9,1669.8 1156.2,1671.5 1156.2,1675.9 1154.519,1677.581 1152.519,1677.581 1151.6,1678.5 ; U40.11@1161.534,1666.133 cw(c1161.184,1665.784) 1161.678,1665.784 cw(c1162.173,1665.784) U40.11@1161.823,1666.133 ; U40.11@1161.534,1667.845 ccw(c1161.184,1668.195) 1161.678,1668.195 ccw(c1162.173,1668.195) U40.11@1161.823,1667.845
  BottomLayer w0.2: v2(1151.763,1646.936) 1151.763,1653.463 1154.7,1656.4 1158.1,1656.4 1159.563,1657.863 v2(1159.563,1659.674)
XUTXD1: J1.223 U41.11 UART2.3 | length 90.3
  TopLayer w0.2: J1.223@1143.725,1629.584 1148.384,1629.584 1153.2,1634.4 1153.2,1636.5 1156,1639.3 1159.7,1639.3 1161,1640.6 1161,1651.6 1174.2,1664.8 1176.7,1664.8 1177.25,1665.35 1177.25,1668.45 1176.2,1669.5 1174.1,1669.5 1172,1671.6 1172,1677.931 1173.2,1679.131 1173.2,1680.834 1172.034,1682 1166.7,1682 1165.508,1680.808 UART2.3@1165.508,1679.902 ; UART2.3@1165.508,1681.002 ccw(c1165.508,1681.471) 1165.839,1681.139 ; UART2.3@1165.608,1680.502 cw(c1166.587,1680.502) 1165.895,1681.195 ; UART2.3@1165.808,1680.502 cw(c1167.27,1680.502) 1166.236,1681.536 ; UART2.3@1166.008,1680.502 cw(c1167.953,1680.502) 1166.578,1681.878 ; U41.11@1177.105,1666.056 cw(c1176.756,1665.706) 1177.25,1665.706 cw(c1177.744,1665.706) U41.11@1177.395,1666.056 ; U41.11@1177.105,1667.768 ccw(c1176.756,1668.118) 1177.25,1668.118 ccw(c1177.744,1668.118) U41.11@1177.395,1667.768
XUTXD2: J1.225 R422.2 U42.4 UART3.2 | length 120
  TopLayer w0.2: J1.225@1143.725,1628.784 1149.084,1628.784 1155.6,1635.3 1159,1635.3 1161.8,1638.1 1161.8,1651.2 1174.6,1664 1183.537,1664 1187.4,1667.863 1187.4,1674.534 1184.334,1677.6 1181.2,1677.6 1179.6,1679.2 UART3.2@1179.6,1679.9 ; UART3.2@1179.6,1678.8 cw(c1179.6,1677.834) 1180.283,1678.517 ; UART3.2@1179.9,1679.3 ccw(c1180.866,1679.3) 1180.183,1678.617 ; UART3.2@1180.1,1679.3 ccw(c1181.549,1679.3) 1180.524,1678.276 ; v2(1198.2,1652.6) 1201.5,1652.6 1203.019,1651.081 1203.019,1649.386 R422.2@1201.73,1648.098 ; R422.2@1201.78,1648.498 ccw(c1201.78,1649.343) 1202.378,1648.745 ; R422.2@1201.98,1648.098 cw(c1202.584,1648.098) R422.2@1202.157,1648.524 ; R422.2@1202.18,1648.098 cw(c1203.267,1648.098) 1202.498,1648.866 ; 1202.579,1648.946 ccw(c1201.939,1649.586) U42.4@1202.844,1649.586 ; 1202.688,1651.412 cw(c1202.311,1651.036) U42.4@1202.844,1651.036 ; 1202.798,1651.302 ccw(c1203.019,1651.523) U42.4@1203.019,1651.211 ; 1202.92,1649.287 ccw(c1202.621,1649.586) U42.4@1203.044,1649.586
  BottomLayer w0.2: v2(1182.9,1664) 1194.3,1652.6 v2(1198.2,1652.6)
XUTXD3: J1.227 UART4.3 | length 86.4
  TopLayer w0.2: J1.227@1143.715,1627.995 J1.227@1143.722,1627.988 ; J1.227@1143.725,1627.984 1149.784,1627.984 1153.115,1631.315 1159.315,1631.315 1162.65,1634.65 1162.65,1650.85 1173.7,1661.9 1183.134,1661.9 1188.6,1667.366 1188.6,1674.466 1192.4,1678.266 UART4.3@1192.4,1680.3 ; UART4.3@1192.183,1679.855 cw(c1191.66,1679.332) 1192.4,1679.332 cw(c1193.14,1679.332) UART4.3@1192.617,1679.855
YM1: J5.4 LCD40P.39 | length 15.9
  TopLayer w0.2: LCD40P.39@1126.6,1582.6 LCD40P.39@1126.6,1582.8 1126.6,1584 1127.2,1584.6 J5.4@1134.3,1584.6 ; 1133.008,1584.6 cw(c1133.008,1583.308) 1133.922,1584.222 ccw(c1133.008,1583.308) 1133.008,1584.6 ; 1133.008,1584.6 ccw(c1133.008,1585.892) 1133.922,1584.978 cw(c1133.008,1585.892) 1133.008,1584.6 ; 1133.491,1584.6 cw(c1133.491,1583.791) 1134.063,1584.363 ccw(c1133.491,1583.791) 1133.491,1584.6 ; 1133.491,1584.6 ccw(c1133.491,1585.409) 1134.063,1584.837 cw(c1133.491,1585.409) 1133.491,1584.6
YP1: J5.3 LCD40P.40 | length 17.6
  TopLayer w0.2: LCD40P.40@1127.1,1582.8 1127.1,1583.8 1127.5,1584.2 1133,1584.2 1133.6,1583.6 1135.3,1583.6 J5.3@1136.3,1584.6 ; 1135.387,1583.687 cw(c1136.3,1582.773) 1136.3,1584.065 ccw(c1136.3,1582.773) 1135.387,1583.687 ; 1135.387,1583.687 ccw(c1134.473,1584.6) 1135.765,1584.6 cw(c1134.473,1584.6) 1135.387,1583.687 ; 1135.728,1584.028 cw(c1136.3,1583.456) 1136.3,1584.265 ccw(c1136.3,1583.456) 1135.728,1584.028 ; 1135.728,1584.028 ccw(c1135.156,1584.6) 1135.965,1584.6 cw(c1135.156,1584.6) 1135.728,1584.028
pads on no net: BAT1.0 COM1. COM1.1 COM1.4 COM1.6 COM1.9 COM2. COM2.1 COM2.4 COM2.6 COM2.9 CON8. HDMI.14 J1.0 J10.1 J20.1 J30.1 J40.1 LCD40P.A LCD40P.B NET.7 NET.A NET.B NET.C NET.D RST.A RST.B S1.3 S1.4 S1.5 UART4.4 USBOTG.6 UT2.19 UT2.20 UT2.21 UT2.46 UT5.15 UT5.30 UU1.22 UU1.23 UU1.24 UU1.25 UU1.26 UU1.27

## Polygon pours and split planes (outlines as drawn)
GND on TopLayer "TopLayer-GND" (hatched 90Degree grid 0.3 track 0.3, remove dead copper, pour order 0): 1039,1568.8 1222,1568.8 1222,1699.8 1124.4,1699.8 1124.4,1681.6 1105.6,1681.6 1105.6,1699.8 1039,1699.8
GND on BottomLayer "BottomLayer-GND" (hatched 90Degree grid 0.3 track 0.3, remove dead copper, pour order 2): 1039,1568.8 1222,1568.8 1222,1699.8 1124.3,1699.8 1124.3,1681.6 1105.7,1681.6 1105.7,1699.8 1039,1699.8

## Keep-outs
KeepOutLayer:
  lines w0.2: 1039,1571 1035,1571 1035,1698 1039,1698 ; 1222,1571 1226,1571 1226,1697.75 1222,1697.75
  lines w0.254: 1039,1697.7 cw(c1041.025,1697.725) 1041,1699.75 1220,1699.75 cw(c1220,1697.75) 1222,1697.75 1222,1570.75 cw(c1220,1570.75) 1220,1568.75 ; 1039,1697.75 1039,1570.75 ccw(c1041.016,1570.75) 1041.016,1568.734 ; 1041,1568.75 1220.25,1568.75

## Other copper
TopLayer:
  rectangle net GND: 1122.2,1661.1 1127.3,1663.4
  rectangle net GND_AC97: 1116.7,1661 1121.6,1663.4
  rectangle net NetDC_IN_1: 1213.841,1684.096 1218.641,1691.31
  rectangle net GND_AC97: 1085.545,1697.1 1096.721,1698.3
  rectangle net VDD5V: 1107,1582.3 1108.168,1583.3
  rectangle net NetFUSE_2: 1206,1669.2 1209.4,1687.7
  rectangle net 3V3_IO: 1174.8,1648.7 1186.4,1657.7
  rectangle net 3V3_IO: 1174.8,1646.8 1177.1,1649.3
  rectangle net GND: 1199.261,1680.591 1202.969,1684.757
  rectangle net GND_AC97: 1090.8,1680.3 1091.802,1697.764
  rectangle net GND_AC97: 1095.118,1678.5 1097.7,1681.292
BottomLayer:
  rectangle net 3V3_IO: 1174.8,1646.8 1177.1,1654.9

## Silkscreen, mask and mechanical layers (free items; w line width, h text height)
TopOverlay:
  drawing of 163 lines, arcs and shapes, not listed
  text "5V" at 1221.5,1688.75 h1.02 r90
  text "T0" at 1152.4,1683.7 h1.02 r90
  text "R0" at 1154.3,1683.7 h1.02 r90
  text "5V" at 1165.7,1683.7 h1.02 r90
  text "R1" at 1167.1,1683.7 h1.02 r90
  text "T1" at 1168.5,1683.7 h1.02 r90
  text "RT1" at 1169.9,1683.7 h1.02 r90
  text "CT1" at 1171.3,1683.7 h1.02 r90
  text "GND" at 1173.1,1683.7 h1.02 r90
  text "3V3" at 1150.25,1683.5 h1.02 r90
  text "T2" at 1180,1683.5 h1.02 r90
  text "R2" at 1182,1683.5 h1.02 r90
  text "5V" at 1178.3,1683.4 h1.02 r90
  text "GND" at 1184.3,1683.4 h1.02 r90
  text "GND" at 1156.3,1683.3 h1.02 r90
  text "+" at 1083.9,1683.1 h1.52
  text "IO" at 1189.2,1682.3 h1.02 r90
  text "GND" at 1190.5,1682.3 h1.02 r90
  text "NC" at 1191.8,1682.3 h1.02 r90
  text "T3" at 1193.1,1682.3 h1.02 r90
  text "R3" at 1194.4,1682.3 h1.02 r90
  text "5V" at 1195.7,1682.3 h1.02 r90
  text "A" at 1074.522,1680.134 h1.14
  text "C" at 1110.072,1678.184 h1.14
  text "OFF" at 1208.75,1665.75 h1.52 r90
  text "ON" at 1208.75,1661.75 h1.52 r90
  text "C" at 1081,1660 h1.14
  text "A" at 1221.25,1657.5 h1.52 r90
  text "B" at 1221.25,1648 h1.52 r90
  text "A" at 1075.4,1641.3 h1.14
  text "OM3" at 1167.541,1597.885 h0.89
  text "OM5" at 1170.791,1597.885 h0.89
  text "DEVICE" at 1174.041,1597.885 h0.89
  text "OM1" at 1161.4,1597.8 h0.89
  text "OM2" at 1164.341,1597.785 h0.89
  text "TQ210_BOARD_V4" at 1101.59,1597.1 h2
  text "NAND" at 1174.791,1596.135 h0.89
  text "ON" at 1161.7,1595.4 h0.89
  text "OFF" at 1170.791,1595.385 h0.89
  text "OFF" at 1167.5,1595.3 h0.89
  text "OFF" at 1164.341,1595.285 h0.89
  text "2K/5C" at 1174.291,1594.885 h0.89
  text "UART" at 1174.541,1593.135 h0.89
  text "Resistive" at 1143.984,1592.964 h0.8
  text "ON" at 1171.2,1592.4 h0.89
  text "USB" at 1174.9,1591.9 h0.89
  text "touch screen" at 1143.2,1591.7 h0.8
  text "OFF" at 1161.2,1589.8 h0.89
  text "ON" at 1164.6,1589.8 h0.89
  text "ON" at 1167.9,1589.8 h0.89
  text "OFF" at 1170.8,1589.8 h0.89
  text "SD/MMC" at 1174.038,1589.722 h0.89
  text "Capacitive" at 1144,1587.5 h0.8
  text "touch screen" at 1143.1,1586.2 h0.8
  text "B" at 1212.722,1583.934 h1.14
  text "Home/Munu" at 1080.7,1582.4 h1
  text "Enter" at 1071.7,1582.3 h1
  text "OM1" at 1164.4,1578.3 h1.02
  text "OM2" at 1164.4,1575.8 h1.02
  text "ESC" at 1074.2,1574.5 h1
  text "POWER" at 1083.6,1574.3 h1
  text "OM3" at 1164.4,1573.3 h1.02
  text "B" at 1214.822,1571.434 h1.14
  text "OM5" at 1164.4,1570.7 h1.02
